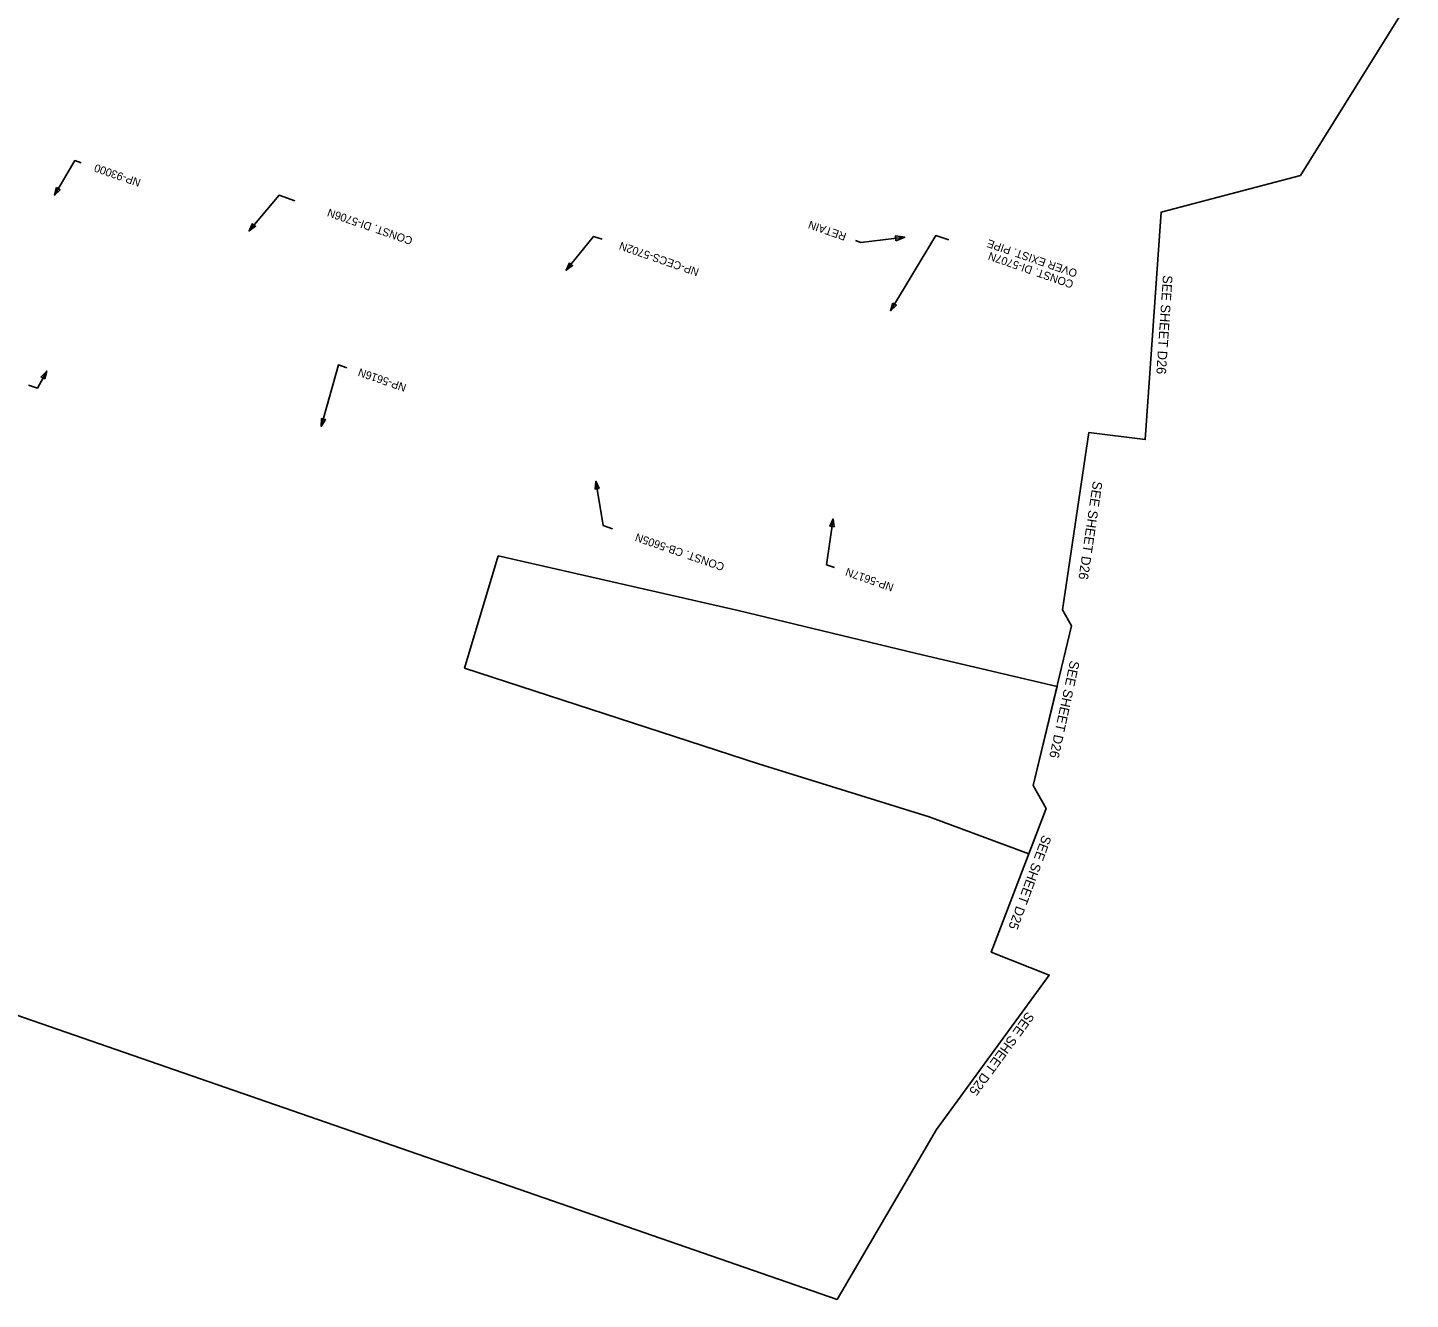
# Model space of a CAD drawing. Extents: x 1607775 to 1609652, y 1093977 to 1095566.
# Drawn here: x 1608751 to 1609615, y 1093977 to 1094771 of the extents above; entities that cross this region are included whole.
import ezdxf

# ---------------------------------------------------------------- set-up
doc = ezdxf.new("R2010")
doc.units = 0
for name, color, linetype in [('RD_HY_Area_SS1', 7, 'Continuous'), ('RD_PD_DR_ErosCtrl', 7, 'Continuous'), ('RD_PD_MedBWall', 7, 'Continuous')]:
    doc.layers.add(name, color=color, linetype=linetype)

msp = doc.modelspace()

# ---------------------------------------------------------------- linework, layer by layer
at = {"layer": 'RD_PD_DR_ErosCtrl'}
for points in [[(1609319.26, 1094082.92), (1609257.16, 1093976.84), (1607774.66, 1094490.39), (1607913.49, 1094758.18), (1608083.85, 1095087.22), (1608184.77, 1095282.94), (1608412.15, 1095241.23), (1608411.67, 1095239.7), (1609329.12, 1094923.25), (1609333.64, 1094914.63), (1609347.07, 1094917.06), (1609439, 1094885.35), (1609428.8, 1094854.27), (1609615.32, 1094789.49), (1609546.66, 1094678.85), (1609459.72, 1094656.09), (1609449.74, 1094513.93), (1609414.43, 1094518.3), (1609397.89, 1094407.56), (1609403.67, 1094397.48), (1609379.74, 1094297.75), (1609387.82, 1094283.49), (1609353.45, 1094193.74), (1609389.72, 1094179.44)], [(1609319.26, 1094082.92), (1609257.16, 1093976.84), (1607774.66, 1094490.39), (1607913.49, 1094758.18), (1608083.85, 1095087.22), (1608184.77, 1095282.94), (1608412.15, 1095241.23), (1608411.67, 1095239.7), (1609329.12, 1094923.25), (1609333.64, 1094914.63), (1609347.07, 1094917.06), (1609439, 1094885.35), (1609428.8, 1094854.27), (1609615.32, 1094789.49), (1609546.66, 1094678.85), (1609459.72, 1094656.09), (1609449.74, 1094513.93), (1609414.43, 1094518.3), (1609397.89, 1094407.56), (1609403.67, 1094397.48), (1609379.74, 1094297.75), (1609387.82, 1094283.49), (1609353.45, 1094193.74), (1609389.72, 1094179.44)], [(1609319.26, 1094082.92), (1609257.16, 1093976.84), (1607774.66, 1094490.39), (1607913.49, 1094758.18), (1608083.85, 1095087.22), (1608184.77, 1095282.94), (1608412.15, 1095241.23), (1608411.67, 1095239.7), (1609329.12, 1094923.25), (1609333.64, 1094914.63), (1609347.07, 1094917.06), (1609439, 1094885.35), (1609428.8, 1094854.27), (1609615.32, 1094789.49), (1609546.66, 1094678.85), (1609459.72, 1094656.09), (1609449.74, 1094513.93), (1609414.43, 1094518.3), (1609397.89, 1094407.56), (1609403.67, 1094397.48), (1609379.74, 1094297.75), (1609387.82, 1094283.49), (1609353.45, 1094193.74), (1609389.72, 1094179.44)], [(1609319.26, 1094082.92), (1609257.16, 1093976.84), (1607774.66, 1094490.39), (1607913.49, 1094758.18), (1608083.85, 1095087.22), (1608184.77, 1095282.94), (1608412.15, 1095241.23), (1608411.67, 1095239.7), (1609329.12, 1094923.25), (1609333.64, 1094914.63), (1609347.07, 1094917.06), (1609439, 1094885.35), (1609428.8, 1094854.27), (1609615.32, 1094789.49), (1609546.66, 1094678.85), (1609459.72, 1094656.09), (1609449.74, 1094513.93), (1609414.43, 1094518.3), (1609397.89, 1094407.56), (1609403.67, 1094397.48), (1609379.74, 1094297.75), (1609387.82, 1094283.49), (1609353.45, 1094193.74), (1609389.72, 1094179.44)], [(1609319.26, 1094082.92), (1609257.16, 1093976.84), (1607774.66, 1094490.39), (1607913.49, 1094758.18), (1608083.85, 1095087.22), (1608184.77, 1095282.94), (1608412.15, 1095241.23), (1608411.67, 1095239.7), (1609329.12, 1094923.25), (1609333.64, 1094914.63), (1609347.07, 1094917.06), (1609439, 1094885.35), (1609428.8, 1094854.27), (1609615.32, 1094789.49), (1609546.66, 1094678.85), (1609459.72, 1094656.09), (1609449.74, 1094513.93), (1609414.43, 1094518.3), (1609397.89, 1094407.56), (1609403.67, 1094397.48), (1609379.74, 1094297.75), (1609387.82, 1094283.49), (1609353.45, 1094193.74), (1609389.72, 1094179.44)], [(1609319.26, 1094082.92), (1609257.16, 1093976.84), (1607774.66, 1094490.39), (1607913.49, 1094758.18), (1608083.85, 1095087.22), (1608184.77, 1095282.94), (1608412.15, 1095241.23), (1608411.67, 1095239.7), (1609329.12, 1094923.25), (1609333.64, 1094914.63), (1609347.07, 1094917.06), (1609439, 1094885.35), (1609428.8, 1094854.27), (1609615.32, 1094789.49), (1609546.66, 1094678.85), (1609459.72, 1094656.09), (1609449.74, 1094513.93), (1609414.43, 1094518.3), (1609397.89, 1094407.56), (1609403.67, 1094397.48), (1609379.74, 1094297.75), (1609387.82, 1094283.49), (1609353.45, 1094193.74), (1609389.72, 1094179.44)], [(1609208.06, 1094311.33), (1609024.39, 1094371.18), (1609045.51, 1094441.29), (1609195.31, 1094407.2), (1609306.86, 1094380.23), (1609394.59, 1094359.62), (1609379.74, 1094297.75), (1609387.82, 1094283.49), (1609376.97, 1094255.18), (1609314.59, 1094278.24)]]:
    msp.add_lwpolyline(points, close=True, dxfattribs=at)
at = {"layer": 'RD_PD_MedBWall'}
for points in [[(1608784.84, 1094686.81), (1608780.86, 1094688.19), (1608768.16, 1094666.53)], [(1608918.29, 1094663.15), (1608908.49, 1094666.54), (1608889.79, 1094644.29)], [(1609110.32, 1094639.04), (1609105.01, 1094640.88), (1609087.89, 1094619.73)], [(1609268.71, 1094638.3), (1609272.08, 1094637.14), (1609299.48, 1094640.33)], [(1609326.92, 1094638.65), (1609318.86, 1094641.44), (1609290.62, 1094594.39)], [(1608751.94, 1094548.01), (1608757.5, 1094546.09), (1608763.32, 1094556.67)], [(1608950.95, 1094558.75), (1608945.58, 1094560.61), (1608934.9, 1094522.16)], [(1609116.85, 1094458.15), (1609111.08, 1094460.15), (1609106.53, 1094487.89)], [(1609255.45, 1094434.02), (1609250.59, 1094435.7), (1609254.68, 1094464.35)]]:
    msp.add_lwpolyline(points, dxfattribs=at)
for points in [[(1608769.49, 1094671.35), (1608768.16, 1094666.53), (1608771.72, 1094670.04)], [(1608891.9, 1094648.82), (1608889.79, 1094644.29), (1608893.88, 1094647.16)], [(1609293.91, 1094638.12), (1609299.48, 1094640.33), (1609293.55, 1094641.2)], [(1609089.92, 1094624.29), (1609087.89, 1094619.73), (1609091.93, 1094622.67)], [(1609292, 1094599.19), (1609290.62, 1094594.39), (1609294.22, 1094597.86)], [(1608762.13, 1094551.82), (1608763.32, 1094556.67), (1608759.86, 1094553.07)], [(1608934.95, 1094527.16), (1608934.9, 1094522.16), (1608937.44, 1094526.47)], [(1609108.59, 1094483.33), (1609106.53, 1094487.89), (1609106.04, 1094482.91)], [(1609255.28, 1094459.39), (1609254.68, 1094464.35), (1609252.72, 1094459.76)]]:
    msp.add_lwpolyline(points, close=True, dxfattribs=at)

# ---------------------------------------------------------------- texts
at = {"layer": 'RD_HY_Area_SS1'}
for s, rotation, p in [('SEE SHEET D26', 266.12323, (1609460.8, 1094616.78)), ('SEE SHEET D26', 261.50654, (1609417.06, 1094488.22)), ('SEE SHEET D26', 257.73099, (1609402.85, 1094376.23)), ('SEE SHEET D25', 249.67266, (1609385.59, 1094267.31)), ('SEE SHEET D25', 233.70788, (1609375.96, 1094156.96))]:
    msp.add_text(s, height=6, rotation=rotation, dxfattribs=at).set_placement(p)
at = {"layer": 'RD_PD_MedBWall'}
for s, p in [('NP-93000', (1608822.54, 1094676.4)), ('CONST. DI-5706N', (1608992.44, 1094640.12)), ('RETAIN', (1609263.43, 1094642.78)), ('NP-CECS-5702N', (1609171.31, 1094620.57)), ('OVER EXIST. PIPE', (1609407.71, 1094619.78)), ('CONST. DI-5707N', (1609405.35, 1094612.97)), ('NP-5616N', (1608988.5, 1094548.39)), ('CONST. CB-5605N', (1609187.22, 1094436.43)), ('NP-5617N', (1609293, 1094423.66))]:
    msp.add_text(s, height=5, rotation=160.90131, dxfattribs=at).set_placement(p)

doc.saveas('drawing.dxf')
